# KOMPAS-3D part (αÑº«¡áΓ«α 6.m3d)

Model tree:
1. Эскиз:1
2. Операция выдавливания:1
     Толщина стенки 1 = 2; Толщина стенки 2 = 8; Расстояние 1 = 1
3. Эскиз:3
4. Операция выдавливания:2
     Толщина стенки 1 = 2; Толщина стенки 2 = 6; Расстояние 1 = 5
5. Эскиз:4
6. Операция выдавливания:3
     Толщина стенки 1 = 2; Толщина стенки 2 = 6; Расстояние 1 = 1
7. Эскиз:5
8. Эскиз:6
9. Операция выдавливания:4
     Толщина стенки 1 = 2; Толщина стенки 2 = 2.5; Расстояние 1 = 50
10. Эскиз:7
11. Вырезать элемент выдавливания:1
     Толщина стенки 2 = 1.5; Расстояние 1 = 40
12. Эскиз:8
13. Операция выдавливания:5
     Толщина стенки 1 = 2; Толщина стенки 2 = 2.5; Расстояние 1 = 50
14. Эскиз:9
15. Вырезать элемент выдавливания:2
     Толщина стенки 2 = 1.5; Расстояние 1 = 40
16. Эскиз:10
17. Операция выдавливания:6
     Толщина стенки 1 = 2; Толщина стенки 2 = 2.5; Расстояние 1 = 10
18. Эскиз:11
19. Операция выдавливания:7
     Толщина стенки 1 = 2; Толщина стенки 2 = 6; Расстояние 1 = 1
20. Эскиз:12
21. Операция выдавливания:8
     Толщина стенки 1 = 2; Толщина стенки 2 = 6; Расстояние 1 = 5
22. Эскиз:13
23. Операция выдавливания:9
     Толщина стенки 1 = 2; Толщина стенки 2 = 8; Расстояние 1 = 1
24. Эскиз:14
25. Вырезать элемент выдавливания:3
     Толщина стенки 2 = 1.5; Расстояние 1 = 23
26. Эскиз:15
27. Вырезать элемент выдавливания:4
     Толщина стенки 2 = 1.5; Расстояние 1 = 1
28. Эскиз:16
29. Вырезать элемент выдавливания:5
     Расстояние 1 = 150
30. Эскиз:20
31. Операция выдавливания:13
     Толщина стенки 1 = 5; Расстояние 1 = 10; Расстояние 2 = 0.4
